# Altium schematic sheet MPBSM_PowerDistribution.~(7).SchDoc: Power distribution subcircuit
size 431 x 279 mm; Date: Not shown in title block; ApprovedBy: Not shown in title block; CheckedBy: Not shown in title block; Author: Not shown in title block; CompanyName: Not shown in title block; DrawnBy: Ricky Zepeda; Engineer: Not shown in title block; Organization: Not shown in title block; Address1: Not shown in title block; Address2: Not shown in title block; Address3: Not shown in title block; Address4: Not shown in title block; DocumentNumber: 2; Revision: Use project parameter SCH_Rev; SheetNumber: 2; SheetTotal: 12; PageSetup: Record=PageOptions¦CenterHorizontal=True¦CenterVertical=True¦PrintScale=0.62¦XCorrection=1.00¦YCorrection=1.00¦PrintKind=0¦BorderSize=5000000¦LeftOffset=0¦BottomOffset=0¦Orientation=2¦PaperLength=1000¦PaperWidth=1000¦Scale=100¦PaperSource=15¦PrintQuality=600¦MediaType=1¦DitherType=10¦PaperKind=Letter¦PrintScaleMode=1
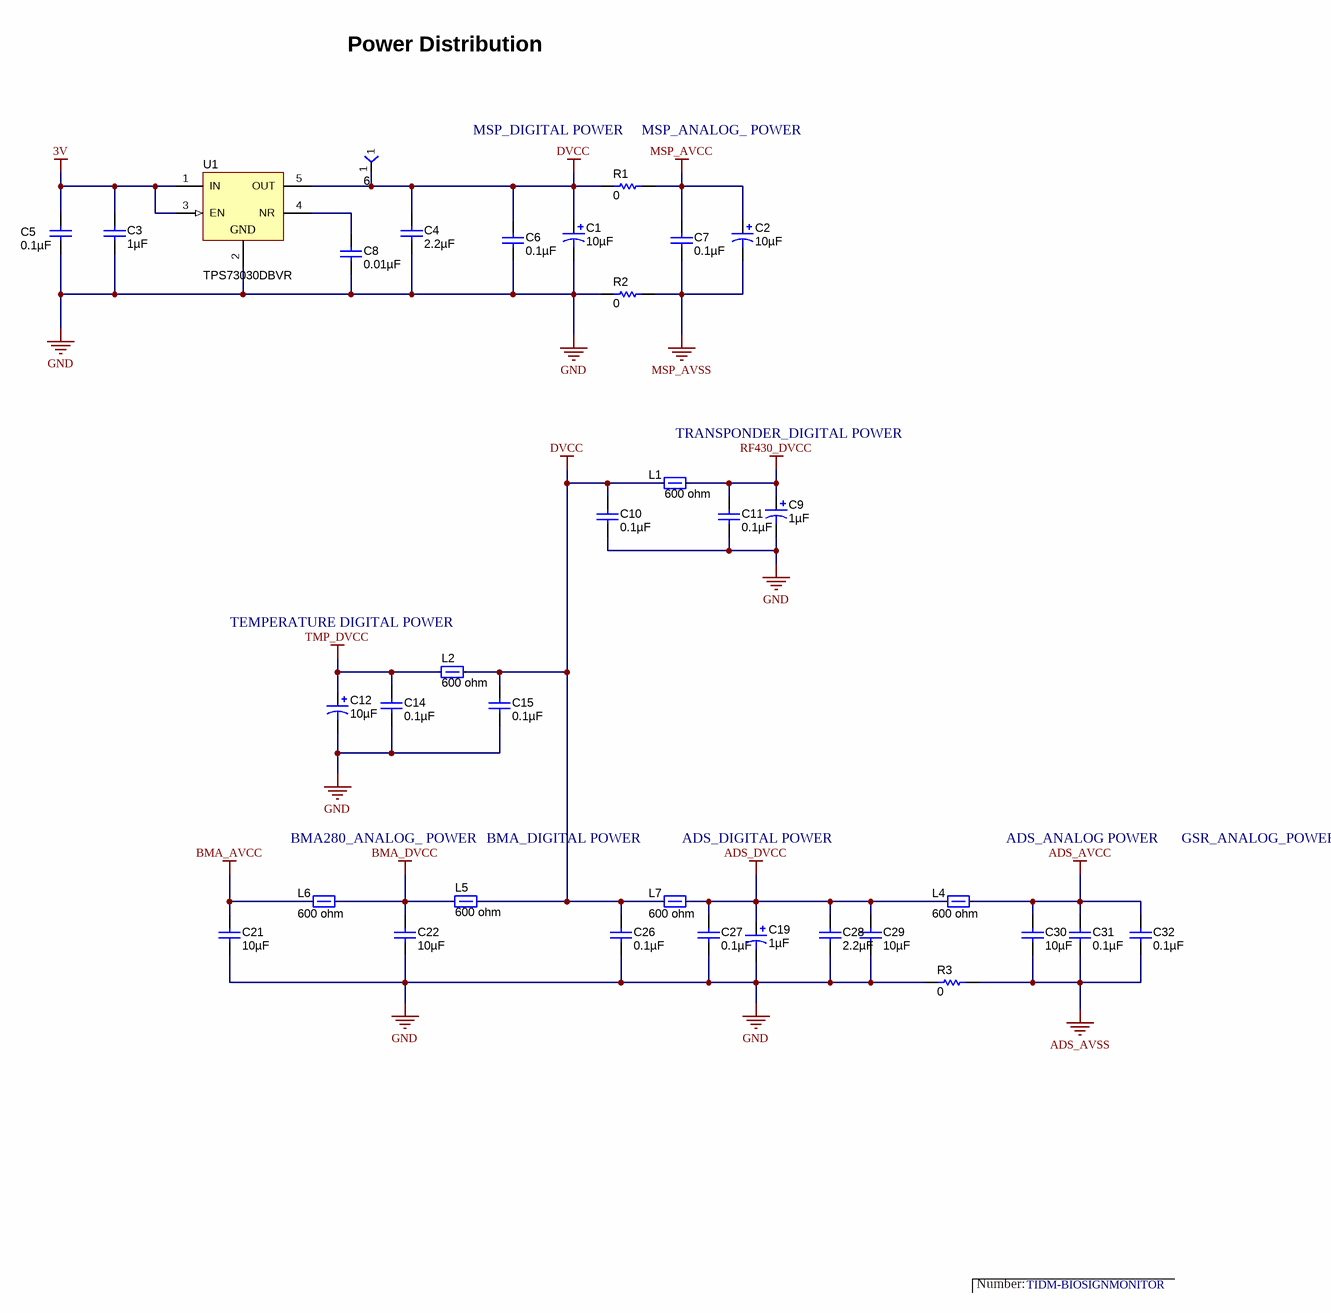
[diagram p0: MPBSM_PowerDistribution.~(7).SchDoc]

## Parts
6  TP-025-SMT  [TP_25MIL-SMT]  (value not drawn)
C1  ValueDisplayed: 10µF  [3216-18]  (hidden comment: 293D106X9010A2TE3)
C2  ValueDisplayed: 10µF  [3216-18]  (hidden comment: 293D106X9010A2TE3)
C3  ValueDisplayed: 1µF  [0402]  (hidden comment: C1005X5R0J105M)
C4  ValueDisplayed: 2.2µF  [0402]  (hidden comment: C1005X5R1C225K050BC)
C5  ValueDisplayed: 0.1µF  [0402]  (hidden comment: C1005X5R1A104K)
C6  ValueDisplayed: 0.1µF  [0402]  (hidden comment: C1005X5R1A104K)
C7  ValueDisplayed: 0.1µF  [0402]  (hidden comment: C1005X5R1A104K)
C8  ValueDisplayed: 0.01µF  [0402]  (hidden comment: C1005X7R1E103K)
C9  ValueDisplayed: 1µF  [3216-18]  (hidden comment: 293D105X9016A2TE3)
C10  ValueDisplayed: 0.1µF  [0402]  (hidden comment: C1005X5R1A104K)
C11  ValueDisplayed: 0.1µF  [0402]  (hidden comment: C1005X5R1A104K)
C12  ValueDisplayed: 10µF  [3216-18]  (hidden comment: 293D106X9010A2TE3)
C14  ValueDisplayed: 0.1µF  [0402]  (hidden comment: C1005X5R1A104K)
C15  ValueDisplayed: 0.1µF  [0402]  (hidden comment: C1005X5R1A104K)
C19  ValueDisplayed: 1µF  [3216-18]  (hidden comment: 293D105X9016A2TE3)
C21  ValueDisplayed: 10µF  [0402]  (hidden comment: CL05A106MQ5NUNC)
C22  ValueDisplayed: 10µF  [0402]  (hidden comment: CL05A106MQ5NUNC)
C26  ValueDisplayed: 0.1µF  [0402]  (hidden comment: C1005X5R1A104K)
C27  ValueDisplayed: 0.1µF  [0402]  (hidden comment: C1005X5R1A104K)
C28  ValueDisplayed: 2.2µF  [0402]  (hidden comment: C1005X5R1C225K050BC)
C29  ValueDisplayed: 10µF  [0402]  (hidden comment: CL05A106MQ5NUNC)
C30  ValueDisplayed: 10µF  [0402]  (hidden comment: CL05A106MQ5NUNC)
C31  ValueDisplayed: 0.1µF  [0402]  (hidden comment: C1005X5R1A104K)
C32  ValueDisplayed: 0.1µF  [0402]  (hidden comment: C1005X5R1A104K)
L1  value 600 ohm  [0603]  (hidden comment: BLM18HG601SN1D)
L2  value 600 ohm  [0603]  (hidden comment: BLM18HG601SN1D)
L4  value 600 ohm  [0603]  (hidden comment: BLM18HG601SN1D)
L5  value 600 ohm  [0603]  (hidden comment: BLM18HG601SN1D)
L6  value 600 ohm  [0603]  (hidden comment: BLM18HG601SN1D)
L7  value 600 ohm  [0603]  (hidden comment: BLM18HG601SN1D)
R1  ValueDisplayed: 0  [0402]  (hidden comment: ERJ-2GE0R00X)
R2  ValueDisplayed: 0  [0402]  (hidden comment: ERJ-2GE0R00X)
R3  ValueDisplayed: 0  [0402]  (hidden comment: ERJ-2GE0R00X)
U1  TPS73030DBVR  [DBV0005A_N]

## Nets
3V: C3.1 C5.1 U1.1(IN) U1.3(EN)
ADS_AVCC: C30.1 C31.1 C32.1 L4.2
ADS_AVSS: C30.2 C31.2 C32.2 R3.2
ADS_DVCC: C19.1(+) C27.1 C28.1 C29.1 L4.1 L7.2
BMA_AVCC: C21.1 L6.1
BMA_DVCC: C22.1 L5.2 L6.2
DVCC: 6.1 C1.1(+) C4.1 C6.1 C10.1 C15.1 C26.1 L1.1 L2.1 L5.1 L7.1 R1.1 U1.5(OUT)
GND: C1.2(-) C3.2 C4.2 C5.2 C6.2 C8.2 C9.2(-) C10.2 C11.2 C12.2(-) C14.2 C15.2 C19.2(-) C21.2 C22.2 C26.2 C27.2 C28.2 C29.2 R2.1 R3.1 U1.2(GND)
MSP_AVCC: C2.1(+) C7.1 R1.2
MSP_AVSS: C2.2(-) C7.2 R2.2
RF430_DVCC: C9.1(+) C11.1 L1.2
TMP_DVCC: C12.1(+) C14.1 L2.2
NetC8_1: C8.1 U1.4(NR)

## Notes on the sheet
- Power Distribution
- (near R1) MSP_DIGITAL POWER
- (near R1) MSP_ANALOG_ POWER
- (near L1) TRANSPONDER_DIGITAL POWER
- TEMPERATURE DIGITAL POWER
- BMA280_ANALOG_ POWER
- BMA_DIGITAL POWER
- ADS_DIGITAL POWER
- ADS_ANALOG POWER
- GSR_ANALOG_POWER
- Number:
- TIDM-BIOSIGNMONITOR

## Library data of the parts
6 = TP-025-SMT: Test Point, O.025"; Manufacturer: STD; Value: STD
C1 C2 C12 = 293D106X9010A2TE3: CAP, TA, 10 µF, 10 V, +/- 10%, 3.4 ohm, SMD; Manufacturer: Vishay-Sprague; Polarized: Y; CompType: Capacitor; Value: 10uF; U/M: EA; Cap_F: 0.00001; Tolerance_%: 10; Value1: 3.4 ohm; Value2: 10V; ESR_ohm: 3.4; IRMS_A: 0.15; TaMin_C: -55; TaMax_C: 125; Cap_Case: A
C3 = C1005X5R0J105M: CAP, CERM, 1 µF, 6.3 V, +/- 20%, X5R, 0402; Manufacturer: TDK; Polarized: N; CompType: Capacitor; Value: 1uF; U/M: EA; Cap_F: 0.000001; Tolerance_%: 20; ESR_ohm: 0.0079; Value1: 0.0079 ohm; VDC_V: 6.3; Value2: 6.3V; TaMin_C: -55; TaMax_C: 85
C4 C28 = C1005X5R1C225K050BC: CAP, CERM, 2.2 µF, 16 V, +/- 10%, X5R, 0402; Manufacturer: TDK; Polarized: N; CompType: Capacitor; Value: 2.2uF; U/M: EA; Cap_F: 0.0000022; Tolerance_%: 10; Value1: Unknown; VDC_V: 16; Value2: 16V; TaMin_C: -55; TaMax_C: 85
C5-C7 C10 C11 C14 C15 C26 C27 C31 C32 = C1005X5R1A104K: CAP, CERM, 0.1 µF, 10 V, +/- 10%, X5R, 0402; Manufacturer: TDK; Polarized: N; CompType: Capacitor; Value: 0.1uF; U/M: EA; Cap_F: 0.0000001; Tolerance_%: 10; ESR_ohm: 0.0186; Value1: 0.0186 ohm; Value2: 10V; TaMin_C: -55; TaMax_C: 85
C8 = C1005X7R1E103K: CAP, CERM, 0.01 µF, 25 V, +/- 10%, X7R, 0402; Manufacturer: TDK; Polarized: N; CompType: Capacitor; Value: 0.01uF; U/M: EA; Cap_F: 0.00000001; Tolerance_%: 10; ESR_ohm: 0.0623; Value1: 0.0623 ohm; VDC_V: 25; Value2: 25V; TaMin_C: -55; TaMax_C: 125
C9 C19 = 293D105X9016A2TE3: CAP, TA, 1 µF, 16 V, +/- 10%, 9.3 ohm, SMD; Manufacturer: Vishay-Sprague; Polarized: Y; CompType: Capacitor; Value: 1uF; U/M: EA; Cap_F: 0.000001; Tolerance_%: 10; Value1: 9.3 ohm; VDC_V: 16; Value2: 16V; ESR_ohm: 9.3; IRMS_A: 0.09; TaMin_C: -55; TaMax_C: 125; Cap_Case: A
C21 C22 C29 C30 = CL05A106MQ5NUNC: CAP, CERM, 10 µF, 6.3 V, +/- 20%, X5R, 0402; Manufacturer: Samsung; Polarized: N; CompType: Capacitor; Value: 10uF; U/M: EA; Cap_F: 0.00001; Tolerance_%: 20; Value1: Unknown; VDC_V: 6.3; Value2: 6.3V; TaMin_C: -55; TaMax_C: 85
L1 L2 L4-L7 = BLM18HG601SN1D: Ferrite Bead, 600 ohm @ 100MHz, 0.2A, 0603; Manufacturer: MuRata; Imax_A: 0.2; DCR_ohm: 1; Value1: 1 ohm; ZTyp@100MHz_Ohm: 600; Ztyp@1GHz_Ohm: 700
R1-R3 = ERJ-2GE0R00X: RES, 0, 5%, 0.063 W, 0402; Manufacturer: Panasonic; CompType: Resistor; Value: 0; Value_Code: 0000; Tolerance_%: 5; Power_W: 0.063; Value2: 0.063W; VDC_V: 50; TempCo: 600 ppm/C; EIA_Code: E24; U/M: EA
U1 = TPS73030DBVR: Single Output High PSRR LDO, 200 mA, Fixed 3 V Output, 2.7 to 5.5 V Input, 5-pin SOT-23 (DBV), -40 to 85 degC, Green (RoHS & no Sb/Br); Manufacturer: Texas Instruments; Alternate Manufacturer: None; Alternate PartNumber: Equivalent; Accuracy(%): 2; Fixed Output Options(V): 3V; Iout(Max)(A): 200mA; Iq(Typ)(mA): 170mA; Rating: Catalog; SubFamily: Single Channel LDO; Vdo(Typ)(mV): 120; Vin(Max)(V): 5.5; Vin(Min)(V): 2.7; Vout Adj(Max)(V): 3; CompType: IC; Value: 3V; Value2: 0.12V @ 200mA; Value3: InputVoltage - Up to 5.5V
